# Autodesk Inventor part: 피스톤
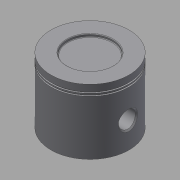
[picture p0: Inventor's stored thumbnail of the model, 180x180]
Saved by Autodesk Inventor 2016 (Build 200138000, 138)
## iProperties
Created: 2016-11
Part Number: 피스톤
Material: 강철, 탄소
Document SubType Name: Modeling
Designer: mduedu
Density: 7.87 g/cm^3
Mass: 273.399 g
Surface Area: 264.986 cm^2
Volume: 34.7394 cm^3
Appearance: 기본값
Author: mduedu
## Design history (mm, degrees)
sketch "스케치1"
  geometry: C1 r 30 at (0, 0); 1 further point
  constraints: 1 centre point, 1 coincident
  dimensions: "d0" = 60 diameter of C1
extrude "돌출1" new body sketch "스케치1" distance "d1" = 50; taper "d2" = 0 deg
sketch "스케치2"
  geometry: C1 r 28 at (0, 0); 1 further point
  constraints: 1 centre point, 1 coincident
  dimensions: "d3" = 56 diameter of C1
extrude "돌출2" cut sketch "스케치2" distance "d4" = 45; taper "d5" = 0 deg
sketch "스케치3"
  geometry: L1 (30, 0)-(30, 50) reference; L2 (30, 45)-(29, 45); L3 (29, 45)-(29, 44); L4 (29, 44)-(30, 44); L5 (30, 44)-(30, 45); L6 (30, 43)-(29, 43); L7 (29, 43)-(29, 42); L8 (29, 42)-(30, 42); L9 (30, 42)-(30, 43); L10 (30, 50)-(-30, 50) reference; L11 (0, 50)-(0, 0)
  constraints: 18 end point, 4 parallel, 3 equal length, 3 perpendicular, 2 horizontal, 2 point on line, 1 midpoint
  dimensions: "d6" = 1 distance of L2.start L2.end; "d8" = 5 distance between parallel lines of L10 L2; "d9" = 1 distance between parallel lines of L6 L4
revolve "회전1" sketch "스케치3" stored, may be unused: angle "d10" = 90 deg
node "작업 평면1"
sketch "스케치4"
  geometry: C1 r 10 at (20, 0); C2 r 6.5 at (20, 0); 1 further point
  constraints: 2 centre point, 1 coincident, 1 horizontal alignment
  dimensions: "d12" = 20 diameter of C1; "d13" = 13 diameter of C2; "d14" = 20 distance of point (0, 0) C1.centre
extrude "돌출3" join sketch "스케치4" stored distance "d15" = 11.75; taper "d16" = 0 deg
extrude "돌출4" cut sketch "스케치4" stored distance "d17" = 72; taper "d18" = 0 deg
fillet "모깎기1" dims "d19" = 3
fillet "모깎기2" dims "d20" = 3
chamfer "모따기1" distance "d21" = 1; stored, may be unused: second distance "d22" = 2, angle "d23" = 45 deg
chamfer "모따기2" distance "d24" = 1; stored, may be unused: second distance "d25" = 2, angle "d26" = 45 deg
sketch "스케치5"
  geometry: C1 r 17.5 at (0, 0); 1 further point
  constraints: 1 centre point, 1 coincident
  dimensions: "d27" = 35 diameter of C1
extrude "돌출5" cut sketch "스케치5" distance "d28" = 2; taper "d29" = 0 deg
fillet "모깎기3" dims "d30" = 0.5
node "솔리드1"
mirror "대칭1"
